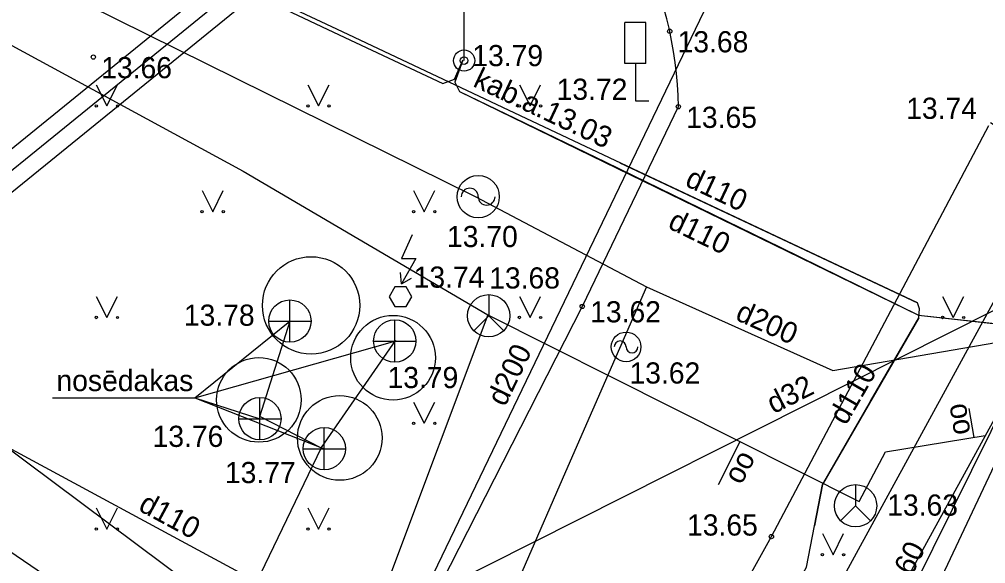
# Model space of a CAD drawing. Extents: x 503904 to 504094, y 304688 to 304960.
# Drawn here: x 504027.93 to 504050.77, y 304864.18 to 304877.05 of the extents above; entities that cross this region are included whole.
import ezdxf

# ---------------------------------------------------------------- set-up
doc = ezdxf.new("R2010")
doc.units = 0
for name, color, linetype in [('APGS_ACRL_####_####_#', 7, 'Continuous'), ('APGS_ACRL_####_TKST_#', 7, 'Continuous'), ('APGS_ELEM_####_####_#', 7, 'Continuous'), ('APGS_VADP_ZSPR_####_#', 7, 'Continuous'), ('APGS_VADP_ZSPR_TKST_#', 7, 'Continuous'), ('CELI_CMAL_####_####_#', 7, 'Continuous'), ('CELI_ELEM_####_####_#', 7, 'Continuous'), ('CKOM_ELEM_####_####_#', 7, 'Continuous'), ('ELEK_VADP_ZSPR_####_#', 7, 'Continuous'), ('ELEK_VADV_VSPR_####_#', 7, 'Continuous'), ('GAZE_ELEM_####_####_#', 7, 'Continuous'), ('GAZE_ELEM_####_TKST_#', 7, 'Continuous'), ('GAZE_VADP_VSP2_####_#', 7, 'Continuous'), ('GAZE_VADP_VSP2_TKST_#', 7, 'Continuous'), ('RAMI_UZMR_####_####_#', 7, 'Continuous'), ('RELJ_AATZ_####_TKST_#', 7, 'Continuous'), ('RELJ_ELEM_####_####_#', 7, 'Continuous'), ('SAKK_ELEM_####_####_#', 7, 'Continuous'), ('SAKK_ELEM_####_TKST_#', 7, 'Continuous'), ('SAKK_IZVK_####_TKST_#', 7, 'Continuous'), ('SAKK_KKAN_####_####_#', 7, 'Continuous'), ('SILT_VADP_NEDR_####_#', 7, 'Continuous'), ('SILT_VADP_UDEN_TKAM_#', 7, 'Continuous'), ('SKAN_DETV_PAST_####_#', 7, 'Continuous'), ('SKAN_ELEM_####_####_#', 7, 'Continuous'), ('SKAN_ELEM_PAST_TKST_#', 7, 'Continuous'), ('SKAN_VADP_PAST_####_#', 7, 'Continuous'), ('SKAN_VADP_PAST_####_I', 7, 'Continuous'), ('SKAN_VADP_PAST_TKST_I', 7, 'Continuous'), ('TERT_ELEM_####_####_#', 7, 'Continuous'), ('UDTK_VADP_NEDR_####_#', 7, 'Continuous'), ('UDTK_VADP_NEDR_TKST_#', 7, 'Continuous'), ('UDTK_VADP_UDEN_####_#', 7, 'Continuous'), ('UDTK_VADP_UDEN_TKST_#', 7, 'Continuous')]:
    doc.layers.add(name, color=color, linetype=linetype)

msp = doc.modelspace()

# ---------------------------------------------------------------- linework, layer by layer
at = {"layer": 'APGS_ACRL_####_####_#'}
for points in [[(504038.416, 304876.08), (504038.244, 304875.672), (504038.226, 304875.558), (504038.279, 304875.45), (504038.331, 304875.343), (504049.181, 304870.056), (504052.142, 304869.731)], [(504042.123, 304873.658), (504049.157, 304870.343)], [(504049.192, 304869.995), (504046.909, 304866.055), (504046.72, 304865.078)]]:
    msp.add_lwpolyline(points, dxfattribs=at)
at = {"layer": 'APGS_ELEM_####_####_#'}
msp.add_line((504038.443, 304876.071), (504038.443, 304877.954), dxfattribs=at)
for radius in [0.25, 0.09]:
    msp.add_circle((504038.443, 304876.071), radius, dxfattribs=at)
at = {"layer": 'APGS_VADP_ZSPR_####_#'}
for points in [[(504034.948, 304837.203), (504032.464, 304838.354), (504032.46, 304838.624), (504032.497, 304838.963), (504034.767, 304843.029), (504037.037, 304847.095), (504041.785, 304855.598), (504046.532, 304864.101), (504046.909, 304866.055), (504048.051, 304868.025), (504049.192, 304869.995), (504049.205, 304870.202), (504049.157, 304870.343), (504042.295, 304873.577), (504035.433, 304876.812), (504031.898, 304878.478), (504020.359, 304883.989), (504008.82, 304889.499), (504008.617, 304889.54), (504008.431, 304889.443), (504006.058, 304885.968)], [(504006.081, 304886.016), (504006.524, 304886.457), (504007.485, 304887.87), (504008.446, 304889.284), (504008.616, 304889.405), (504008.824, 304889.386), (504016.168, 304885.866), (504023.512, 304882.345), (504029.465, 304879.528), (504035.491, 304876.677), (504037.943, 304875.532), (504038.212, 304875.634), (504038.416, 304876.08), (504038.226, 304875.558), (504038.331, 304875.343), (504039.638, 304874.712), (504041.796, 304873.674), (504045.914, 304871.662), (504049.181, 304870.056), (504051.511, 304869.798), (504052.144, 304869.735)]]:
    msp.add_lwpolyline(points, dxfattribs=at)
at = {"layer": 'CELI_CMAL_####_####_#'}
for points in [[(504043.505, 304874.98), (504041.235, 304870.26), (504033.948, 304855.96), (504026.066, 304840.762)], [(504032.161, 304840.294), (504039.525, 304853.703), (504045.705, 304864.823), (504050.845, 304874.537)], [(504032.559, 304836.774), (504041.261, 304852.587), (504047.431, 304863.915), (504052.724, 304873.608), (504051.009, 304874.521), (504050.882, 304874.598)], [(504054.623, 304874.25), (504048.611, 304863.3), (504042.44, 304852.018), (504033.541, 304835.699)]]:
    msp.add_lwpolyline(points, dxfattribs=at)
msp.add_arc((504034.812, 304874.895), 8.694, 0.5576, 28.2626, dxfattribs=at)
at = {"layer": 'CELI_ELEM_####_####_#'}
for p, q in [((504042.739, 304876.967), (504042.239, 304876.967)), ((504042.239, 304875.998), (504042.239, 304876.967)), ((504042.739, 304875.998), (504042.739, 304876.967)), ((504042.739, 304875.998), (504042.239, 304875.998)), ((504042.493, 304875.998), (504042.493, 304875.12)), ((504042.493, 304875.12), (504042.808, 304875.12))]:
    msp.add_line(p, q, dxfattribs=at)
at = {"layer": 'CKOM_ELEM_####_####_#'}
msp.add_line((504036.962, 304870.792), (504037.203, 304870.931), dxfattribs=at)
msp.add_lwpolyline([(504037.211, 304871.954), (504036.962, 304871.391), (504037.298, 304871.391), (504036.962, 304870.792), (504036.94, 304871.062)], dxfattribs=at)
msp.add_lwpolyline([(504036.806, 304870.262), (504037.072, 304870.262), (504037.205, 304870.492), (504037.072, 304870.723), (504036.806, 304870.723), (504036.673, 304870.492)], close=True, dxfattribs=at)
at = {"layer": 'ELEK_VADP_ZSPR_####_#'}
msp.add_lwpolyline([(504002.84, 304883.907), (504013.238, 304874.636), (504017.897, 304871.307), (504022.559, 304867.983), (504028.527, 304863.916), (504031.948, 304861.583), (504040.554, 304855.614), (504044.535, 304852.853)], dxfattribs=at)
at = {"layer": 'ELEK_VADV_VSPR_####_#'}
msp.add_line((504017.859, 304874.234), (504045.046, 304853.939), dxfattribs=at)
at = {"layer": 'GAZE_ELEM_####_####_#'}
for centre, radius in [((504038.775, 304872.855), 0.5), ((504042.271, 304869.305), 0.35)]:
    msp.add_circle(centre, radius, dxfattribs=at)
for centre, radius, start, end in [((504038.575, 304872.855), 0.2, 0, 180), ((504038.975, 304872.855), 0.2, 180, 0), ((504042.131, 304869.305), 0.14, 0, 180), ((504042.411, 304869.305), 0.14, 180, 0)]:
    msp.add_arc(centre, radius, start, end, dxfattribs=at)
at = {"layer": 'GAZE_VADP_VSP2_####_#'}
for points in [[(503989.698, 304903.414), (504000, 304898.037), (504010.212, 304892.707), (504011.048, 304889.414), (504011.884, 304886.121), (504025.295, 304879.492), (504038.706, 304872.862), (504042.754, 304870.726), (504047.158, 304868.745), (504052.063, 304869.587)], [(504042.754, 304870.726), (504040.842, 304866.35), (504038.93, 304861.973), (504035.12, 304854.33), (504031.31, 304846.687), (504029.002, 304842.057), (504026.694, 304837.426), (504024.595, 304833.216), (504022.496, 304829.005), (504019.148, 304822.29), (504017.375, 304818.733), (504013.61, 304817.132), (504006.805, 304802.964), (504000, 304788.796), (503996.994, 304782.538), (503993.988, 304776.279), (503986.861, 304755.747)]]:
    msp.add_lwpolyline(points, dxfattribs=at)
at = {"layer": 'RAMI_UZMR_####_####_#'}
msp.add_lwpolyline([(503923.253, 304801.015), (503981.982, 304759.672), (503995.48, 304748.813), (504027.75, 304817.255), (504060.02, 304885.696), (504048.875, 304885.773), (504036.803, 304888.853), (503994.536, 304908.303), (503981.123, 304894.75), (503978.518, 304892.436), (503950.886, 304846.726), (503923.253, 304801.015)], dxfattribs=at)
at = {"layer": 'RELJ_ELEM_####_####_#'}
for centre in [(504043.302, 304876.765), (504029.68, 304876.154), (504043.505, 304874.98), (504041.235, 304870.26), (504045.705, 304864.823)]:
    msp.add_circle(centre, 0.05, dxfattribs=at)
at = {"layer": 'SAKK_ELEM_####_####_#'}
for p, q in [((504039.024, 304870.041), (504039.378, 304869.687)), ((504047.695, 304865.55), (504048.049, 304865.196))]:
    msp.add_line(p, q, dxfattribs=at)
for points in [[(504039.024, 304870.541), (504039.024, 304870.041), (504038.67, 304869.687)], [(504047.695, 304866.05), (504047.695, 304865.55), (504047.341, 304865.196)]]:
    msp.add_lwpolyline(points, dxfattribs=at)
for centre in [(504039.024, 304870.041), (504047.695, 304865.55)]:
    msp.add_circle(centre, 0.5, dxfattribs=at)
at = {"layer": 'SAKK_IZVK_####_TKST_#'}
for p, q in [((504050.372, 304867.848), (504050.486, 304867.165)), ((504044.458, 304866.05), (504044.97, 304867.068))]:
    msp.add_line(p, q, dxfattribs=at)
at = {"layer": 'SAKK_KKAN_####_####_#'}
for points in [[(503986.316, 304899.997), (504000, 304892.196), (504013.782, 304884.178), (504021.554, 304879.802), (504033.218, 304873.459), (504039.007, 304870.064), (504043.395, 304867.859), (504047.782, 304865.655), (504048.401, 304866.822), (504050.758, 304867.21)], [(504039.007, 304870.064), (504036.678, 304863.872), (504034.349, 304857.68), (504031.408, 304852.312), (504030.269, 304850.237), (504027.088, 304844.191), (504022.232, 304834.693), (504020.138, 304830.591), (504009.306, 304809.848), (504000, 304790.89), (503998.089, 304787.127), (503992.169, 304775.655), (503986.248, 304764.183), (503984.196, 304757.891)]]:
    msp.add_lwpolyline(points, dxfattribs=at)
at = {"layer": 'SILT_VADP_NEDR_####_#'}
msp.add_lwpolyline([(504022.461, 304869.185), (504044.321, 304886.935)], dxfattribs=at)
at = {"layer": 'SILT_VADP_UDEN_TKAM_#'}
for points in [[(504021.948, 304869.284), (504043.838, 304887.058)], [(504022.974, 304869.086), (504044.804, 304886.812)]]:
    msp.add_lwpolyline(points, dxfattribs=at)
at = {"layer": 'SKAN_DETV_PAST_####_#'}
for centre, radius in [((504034.827, 304870.286), 1.15), ((504036.763, 304869.049), 1), ((504033.592, 304868.053), 1), ((504035.504, 304867.153), 1)]:
    msp.add_circle(centre, radius, dxfattribs=at)
at = {"layer": 'SKAN_ELEM_####_####_#'}
for p, q in [((504034.324, 304869.415), (504034.324, 304870.415)), ((504033.824, 304869.915), (504034.824, 304869.915)), ((504036.805, 304868.944), (504036.805, 304869.944)), ((504036.305, 304869.444), (504037.305, 304869.444)), ((504033.616, 304867.108), (504033.616, 304868.108)), ((504033.116, 304867.608), (504034.116, 304867.608)), ((504035.138, 304866.4), (504035.138, 304867.4)), ((504034.638, 304866.9), (504035.638, 304866.9))]:
    msp.add_line(p, q, dxfattribs=at)
for centre in [(504034.324, 304869.915), (504036.805, 304869.444), (504033.616, 304867.608), (504035.138, 304866.9)]:
    msp.add_circle(centre, 0.5, dxfattribs=at)
at = {"layer": 'SKAN_ELEM_PAST_TKST_#'}
for q in [(504034.324, 304869.915), (504036.805, 304869.444), (504035.138, 304866.9)]:
    msp.add_line((504032.075, 304868.099), q, dxfattribs=at)
msp.add_lwpolyline([(504028.714, 304868.099), (504032.075, 304868.099), (504033.616, 304867.608)], dxfattribs=at)
at = {"layer": 'SKAN_VADP_PAST_####_#'}
for points in [[(504035.073, 304866.911), (504033.617, 304867.663), (504034.333, 304869.921)], [(504013.944, 304825.238), (504014.361, 304825.537), (504026.051, 304848.216), (504035.076, 304866.925), (504036.831, 304869.467)]]:
    msp.add_lwpolyline(points, dxfattribs=at)
at = {"layer": 'SKAN_VADP_PAST_####_I'}
msp.add_lwpolyline([(504023.783, 304835.985), (504032.733, 304853.578), (504047.208, 304883.667), (504054.39, 304883.114), (504058.648, 304882.787)], dxfattribs=at)
at = {"layer": 'TERT_ELEM_####_####_#'}
for p, q in [((504029.75, 304875.5), (504030, 304875)), ((504030, 304875), (504030.25, 304875.5)), ((504034.75, 304875.5), (504035, 304875)), ((504035, 304875), (504035.25, 304875.5)), ((504039.75, 304875.5), (504040, 304875)), ((504040, 304875), (504040.25, 304875.5)), ((504032.25, 304873), (504032.5, 304872.5)), ((504032.5, 304872.5), (504032.75, 304873)), ((504037.25, 304873), (504037.5, 304872.5)), ((504037.5, 304872.5), (504037.75, 304873)), ((504029.75, 304870.5), (504030, 304870)), ((504030, 304870), (504030.25, 304870.5)), ((504039.75, 304870.5), (504040, 304870)), ((504040, 304870), (504040.25, 304870.5)), ((504049.75, 304870.5), (504050, 304870)), ((504050, 304870), (504050.25, 304870.5)), ((504037.25, 304868), (504037.5, 304867.5)), ((504037.5, 304867.5), (504037.75, 304868)), ((504029.75, 304865.5), (504030, 304865)), ((504030, 304865), (504030.25, 304865.5)), ((504034.75, 304865.5), (504035, 304865)), ((504035, 304865), (504035.25, 304865.5)), ((504046.912, 304864.894), (504047.162, 304864.394)), ((504047.162, 304864.394), (504047.412, 304864.894))]:
    msp.add_line(p, q, dxfattribs=at)
for centre, radius in [((504029.75, 304875), 0.028), ((504030.25, 304875), 0.0263), ((504034.75, 304875), 0.028), ((504035.25, 304875), 0.0263), ((504039.75, 304875), 0.028), ((504040.25, 304875), 0.0263), ((504032.25, 304872.5), 0.028), ((504032.75, 304872.5), 0.0263), ((504037.25, 304872.5), 0.028), ((504037.75, 304872.5), 0.0263), ((504029.75, 304870), 0.028), ((504030.25, 304870), 0.0263), ((504039.75, 304870), 0.028), ((504040.25, 304870), 0.0263), ((504049.75, 304870), 0.028), ((504050.25, 304870), 0.0263), ((504037.25, 304867.5), 0.028), ((504037.75, 304867.5), 0.0263), ((504029.75, 304865), 0.028), ((504030.25, 304865), 0.0263), ((504034.75, 304865), 0.028), ((504035.25, 304865), 0.0263), ((504046.911, 304864.393), 0.028), ((504047.411, 304864.393), 0.0263)]:
    msp.add_circle(centre, radius, dxfattribs=at)
at = {"layer": 'UDTK_VADP_NEDR_####_#'}
msp.add_lwpolyline([(504018.286, 304854.806), (504025.161, 304857.88), (504029.291, 304859.726), (504035.8, 304862.529), (504046.496, 304867.919), (504053.241, 304871.318)], dxfattribs=at)
at = {"layer": 'UDTK_VADP_UDEN_####_#'}
for points in [[(504035.876, 304862.497), (503979.246, 304893.082)], [(504052.599, 304884.688), (504054.563, 304874.709), (504047.684, 304860.837), (504037.414, 304840.144), (504031.385, 304827.996), (504014.788, 304793.579), (504000, 304762.914), (503998.944, 304760.723), (503997.887, 304758.532), (503994.035, 304750.096), (503993.994, 304750.008)]]:
    msp.add_lwpolyline(points, dxfattribs=at)

# ---------------------------------------------------------------- texts
at = {"layer": 'APGS_ACRL_####_TKST_#'}
for rotation, p in [(334.7663, (504043.637, 304873.125)), (334.0216, (504043.232, 304872.124)), (59.9102, (504047.465, 304867.432))]:
    msp.add_text('d110', height=0.5, rotation=rotation, dxfattribs=at).set_placement(p)
at = {"layer": 'APGS_VADP_ZSPR_TKST_#'}
msp.add_text('kab.a.13.03', height=0.5, rotation=334.7632, dxfattribs=at).set_placement((504038.627, 304875.472))
at = {"layer": 'GAZE_ELEM_####_TKST_#'}
for s, p in [('13.70', (504038.038, 304871.664)), ('13.62', (504042.351, 304868.439))]:
    msp.add_text(s, height=0.5, dxfattribs=at).set_placement(p)
at = {"layer": 'GAZE_VADP_VSP2_TKST_#'}
msp.add_text('d200', height=0.5, rotation=335.7809, dxfattribs=at).set_placement((504044.826, 304869.958))
at = {"layer": 'RELJ_AATZ_####_TKST_#'}
for s, p in [(' 13.68', (504043.302, 304876.265)), (' 13.79', (504038.451, 304875.939)), (' 13.66', (504029.68, 304875.654)), (' 13.72', (504040.443, 304875.143)), (' 13.74', (504048.705, 304874.694)), (' 13.65', (504043.505, 304874.48)), (' 13.74', (504037.064, 304870.704)), (' 13.62', (504041.235, 304869.885)), (' 13.65', (504043.525, 304864.847))]:
    msp.add_text(s, height=0.5, dxfattribs=at).set_placement(p)
at = {"layer": 'SAKK_ELEM_####_TKST_#'}
for s, p in [('13.68', (504039.035, 304870.685)), ('13.63', (504048.442, 304865.318))]:
    msp.add_text(s, height=0.5, dxfattribs=at).set_placement(p)
at = {"layer": 'SAKK_IZVK_####_TKST_#'}
for rotation, p in [(279.5179, (504049.912, 304867.935)), (62.0685, (504044.991, 304866.027))]:
    msp.add_text('oo', height=0.5, rotation=rotation, dxfattribs=at).set_placement(p)
at = {"layer": 'SKAN_ELEM_PAST_TKST_#'}
for s, p in [('13.78', (504031.819, 304869.805)), ('nosēdakas', (504028.808, 304868.261)), ('13.79', (504036.632, 304868.332)), ('13.76', (504031.08, 304866.942)), ('13.77', (504032.789, 304866.086))]:
    msp.add_text(s, height=0.5, dxfattribs=at).set_placement(p)
at = {"layer": 'SKAN_VADP_PAST_TKST_I'}
msp.add_text('d200', height=0.5, rotation=64.2071, dxfattribs=at).set_placement((504039.409, 304867.873))
at = {"layer": 'UDTK_VADP_NEDR_TKST_#'}
msp.add_text('d32', height=0.5, rotation=26.7456, dxfattribs=at).set_placement((504045.757, 304867.714))
at = {"layer": 'UDTK_VADP_UDEN_TKST_#'}
for s, rotation, p in [('d110', 331.6271, (504030.718, 304865.454)), ('d160', 63.6045, (504048.695, 304863.212))]:
    msp.add_text(s, height=0.5, rotation=rotation, dxfattribs=at).set_placement(p)

doc.saveas('drawing.dxf')
